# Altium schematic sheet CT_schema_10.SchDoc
size 274 x 160 mm
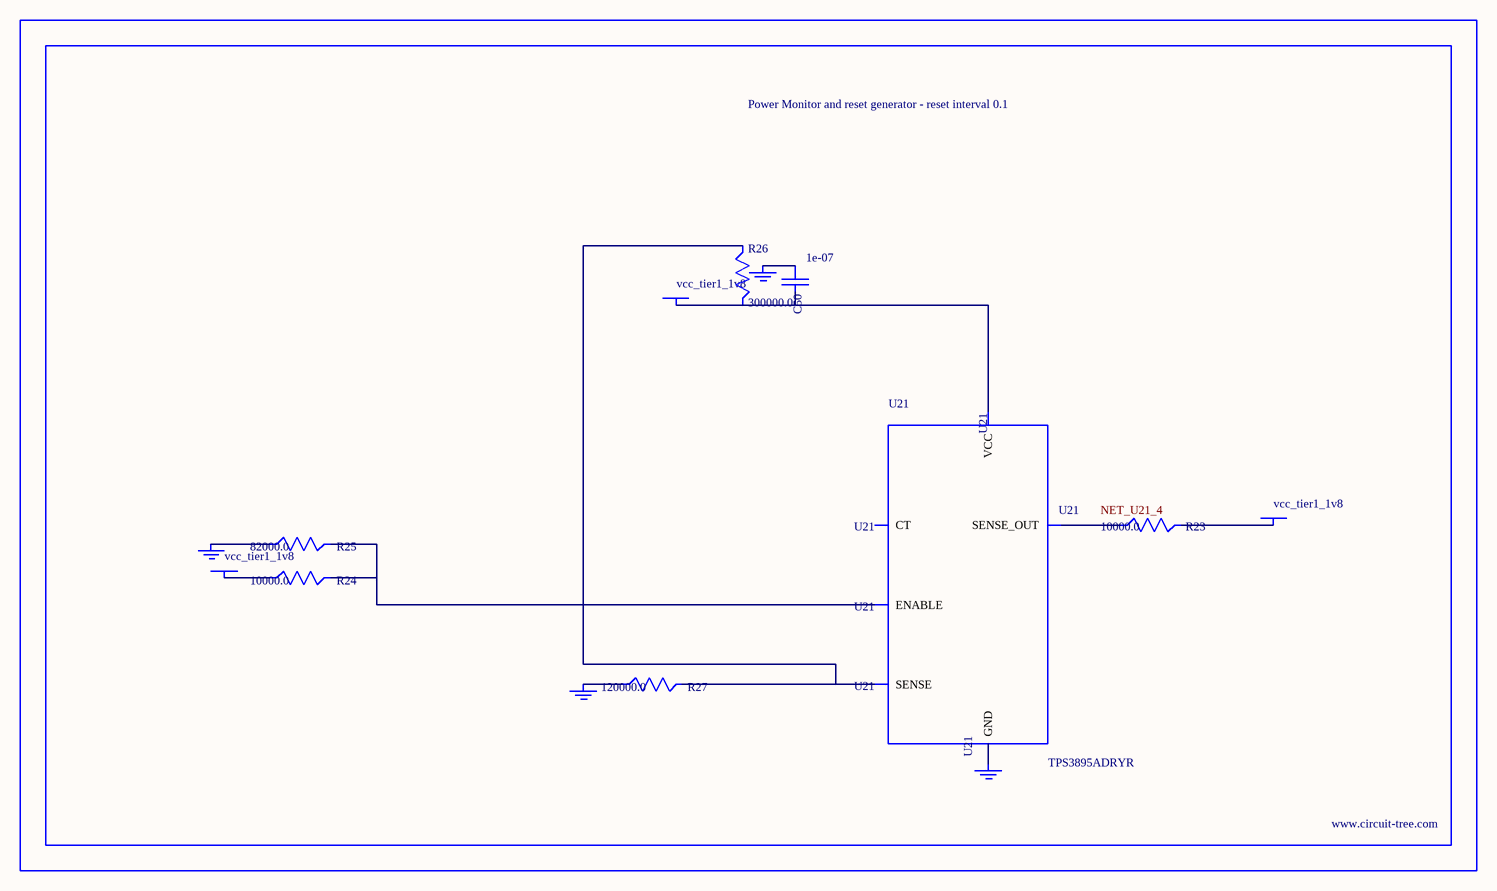
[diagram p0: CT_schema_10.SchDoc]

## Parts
BORDER9  (no value)
C50  1e-07  [C0402]
GND_INSTANCE_9_0  (no value)
GND_INSTANCE_9_1  (no value)
GND_INSTANCE_9_2  (no value)
GND_INSTANCE_9_3  (no value)
POWER_INSTANCE_9_0  vcc_tier1_1v8
POWER_INSTANCE_9_1  vcc_tier1_1v8
POWER_INSTANCE_9_2  vcc_tier1_1v8
R23  10000.0  [R0603]
R24  10000.0  [R0603]
R25  82000.0  [R0603]
R26  300000.0  [R0603]
R27  120000.0  [R0603]
U21  TPS3895ADRYR  [SON-6]

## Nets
NetC50_1: C50.1 GND_INSTANCE_9_2.0(GND)
NetC50_2: C50.2 POWER_INSTANCE_9_2.0(PWR) R26.2 U21.6(VCC)
NetGND_INSTANCE_9_0_0: GND_INSTANCE_9_0.0(GND) R25.1
NetGND_INSTANCE_9_1_0: GND_INSTANCE_9_1.0(GND) R27.1
NetGND_INSTANCE_9_3_0: GND_INSTANCE_9_3.0(GND) U21.2(GND)
NetPOWER_INSTANCE_9_0_0: POWER_INSTANCE_9_0.0(PWR) R24.1
NetPOWER_INSTANCE_9_1_0: POWER_INSTANCE_9_1.0(PWR) R23.2
NetR23_1: R23.1 U21.4(SENSE_OUT)
NetR24_2: R24.2 R25.2 U21.1(ENABLE)
NetR26_1: R26.1 R27.2 U21.3(SENSE)

Not connected (* = marked no-connect by the designer): U21 5(CT)

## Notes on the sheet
- Labels drawn without touching a wire or pin: NET_U21_4

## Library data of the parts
BORDER9 = BORDER_PAGE9
C50 = C0402C104K3RACTU
GND_INSTANCE_9_0-GND_INSTANCE_9_3 = GND
POWER_INSTANCE_9_0-POWER_INSTANCE_9_2 = PWR
R23 R24 = RC0603JR-0710KL
R25 = RC0603JR-0782KL
R26 = RC0603JR-07300KL
R27 = RC0603JR-07120KL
